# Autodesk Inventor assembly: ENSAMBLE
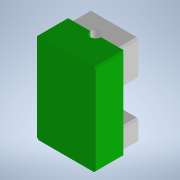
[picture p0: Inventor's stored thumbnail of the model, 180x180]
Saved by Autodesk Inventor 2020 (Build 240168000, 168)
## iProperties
Created: 2022-10
Part Number: ENSAMBLE
Document SubType Name: Assembly
Designer: SEBAS
Author: SEBAS
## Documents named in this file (4)
- D:\TRABAJO UNIVERSIDAD\SISTEMA CALEFACTOR VERSION 2\ENSAMBLE.iam
- D:\TRABAJO UNIVERSIDAD\SISTEMA CALEFACTOR VERSION 2\CALEFACTOR VERSION 2.ipt
- D:\TRABAJO UNIVERSIDAD\SISTEMA CALEFACTOR VERSION 2\ABRAZADERA 2.ipt
- D:\TRABAJO UNIVERSIDAD\SISTEMA CALEFACTOR VERSION 2\ABRAZADERA 1.ipt
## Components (3 placed, 3 different names)
1. CALEFACTOR VERSION 2:1 — Nivelación:1, Nivelación:2, Nivelación:3, Coincidencia:1, Coincidencia:2, Coincidencia:3, Coincidencia:4, Coincidencia:5, Coincidencia:6
2. ABRAZADERA 2:1 — Coincidencia:1, Coincidencia:2, Coincidencia:3
3. ABRAZADERA 1:1 — Coincidencia:4, Coincidencia:5, Coincidencia:6
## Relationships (9: Mate 6, Flush 3)
- Nivelación:1 [Flush]: CALEFACTOR VERSION 2:1
- Nivelación:2 [Flush]: CALEFACTOR VERSION 2:1
- Nivelación:3 [Flush]: CALEFACTOR VERSION 2:1
- Coincidencia:1 [Mate]: CALEFACTOR VERSION 2:1 ↔ ABRAZADERA 2:1
- Coincidencia:2 [Mate]: CALEFACTOR VERSION 2:1 ↔ ABRAZADERA 2:1
- Coincidencia:3 [Mate]: CALEFACTOR VERSION 2:1 ↔ ABRAZADERA 2:1
- Coincidencia:4 [Mate]: CALEFACTOR VERSION 2:1 ↔ ABRAZADERA 1:1
- Coincidencia:5 [Mate]: CALEFACTOR VERSION 2:1 ↔ ABRAZADERA 1:1
- Coincidencia:6 [Mate]: CALEFACTOR VERSION 2:1 ↔ ABRAZADERA 1:1
